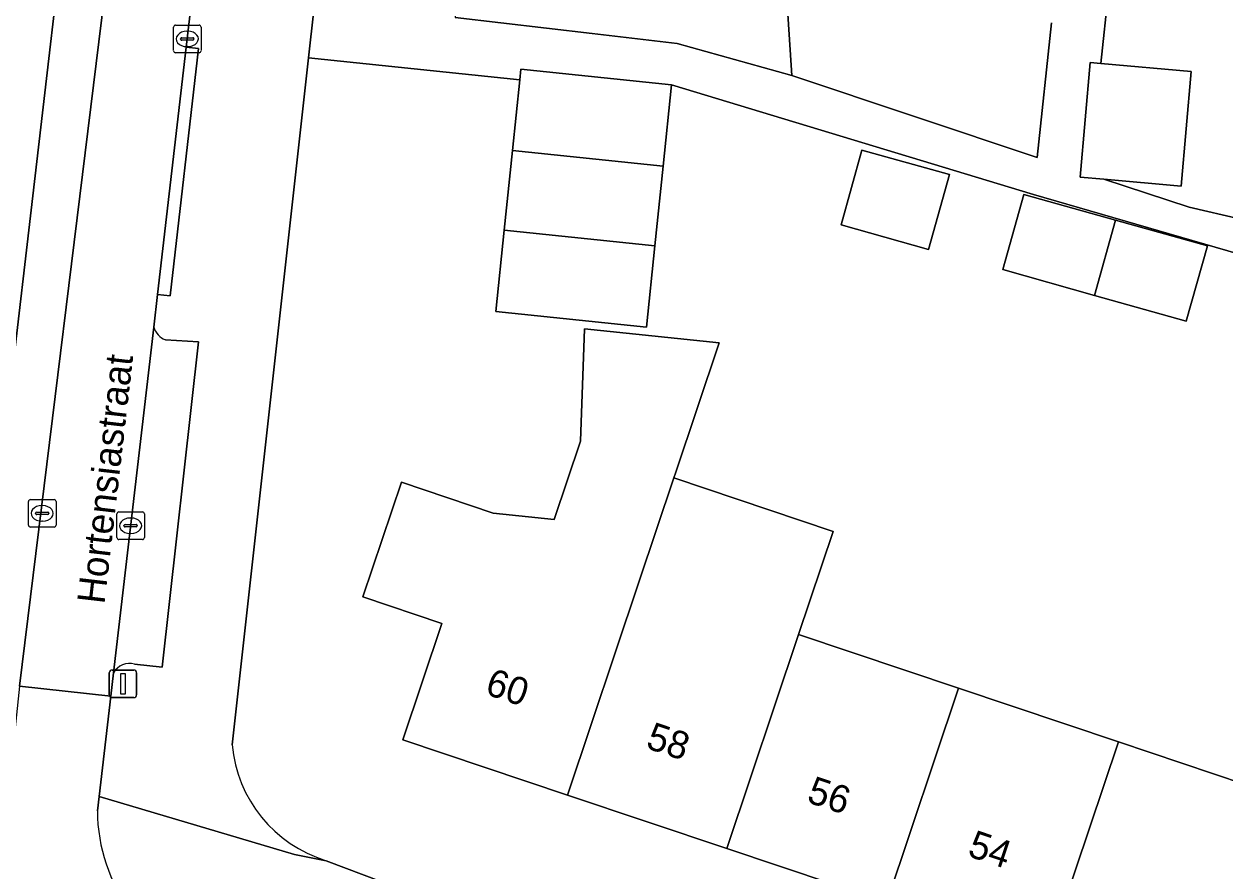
# Model space of a CAD drawing. Extents: x 161692 to 162379, y 380760 to 381678.
# Drawn here: x 162005.46 to 162049.01, y 380962.24 to 380992.94 of the extents above; entities that cross this region are included whole.
import ezdxf

# ---------------------------------------------------------------- set-up
doc = ezdxf.new("R2010")
doc.units = 0
for name, color, linetype in [('IMGEO_Erf', 7, 'Continuous'), ('IMGEO_Kolk', 7, 'Continuous'), ('IMGEO_Lichtmast', 7, 'Continuous'), ('IMGEO_Openbare_ruimte_label', 7, 'Continuous'), ('IMGEO_Pand', 7, 'Continuous'), ('IMGEO_Pand_nummerreeks', 7, 'Continuous'), ('IMGEO_Parkeervlak_open', 7, 'Continuous'), ('IMGEO_Rijbaan_lokaal_open', 7, 'Continuous'), ('IMGEO_Voetpad_open', 7, 'Continuous')]:
    doc.layers.add(name, color=color, linetype=linetype)

msp = doc.modelspace()

# ---------------------------------------------------------------- linework, layer by layer
at = {"layer": 'IMGEO_Erf'}
for points in [[(162049.147, 381005.801), (162046.062, 381006.135), (162045.505, 381000.982), (162048.591, 381000.649), (162048.242, 380997.421), (162047.85, 380993.799), (162044.785, 380994.13), (162044.509, 380991.51), (162047.791, 380991.221), (162047.425, 380987.065), (162044.621, 380987.312), (162047.712, 380986.308), (162057.079, 380984.131)], [(162032.862, 380997.951), (162033.305, 380991.072), (162042.204, 380988.097), (162042.717, 380992.979)], [(162058.561, 380975.708), (162055.003, 380977.223), (162049.4, 380978.891), (162051.158, 380984.129), (162042.064, 380986.765), (162028.946, 380990.739), (162028.64, 380987.79), (162028.341, 380984.905), (162028.036, 380981.959), (162022.566, 380982.526), (162022.872, 380985.472), (162023.171, 380988.357), (162023.436, 380990.915), (162015.772, 380991.71), (162013.002, 380966.811)], [(162053.992, 380955.32), (162048.296, 380957.232), (162042.545, 380959.162), (162036.746, 380961.108), (162030.947, 380963.054), (162025.17, 380964.992), (162019.198, 380966.996), (162020.614, 380971.218), (162017.75, 380972.18), (162019.144, 380976.334), (162022.475, 380975.216), (162024.69, 380974.984), (162025.641, 380977.82), (162025.786, 380981.89), (162030.665, 380981.384), (162029.084, 380976.665), (162029.026, 380976.493), (162034.805, 380974.553), (162033.55, 380970.812), (162039.349, 380968.866), (162045.148, 380966.92), (162050.899, 380964.99)], [(162016.411, 380962.617), (162029.526, 380957.667), (162046.576, 380951.828), (162059.92, 380947.792)]]:
    msp.add_lwpolyline(points, dxfattribs=at)
for points in [[(162035.089, 380985.66), (162035.847, 380988.372), (162039.017, 380987.485), (162038.259, 380984.773)], [(162040.952, 380984.038), (162041.715, 380986.766), (162045.042, 380985.835), (162048.374, 380984.903), (162047.611, 380982.175), (162044.279, 380983.107)]]:
    msp.add_lwpolyline(points, close=True, dxfattribs=at)
msp.add_arc((162017.857, 380967.275), 4.877, 185.4543, 252.7561, dxfattribs=at)
at = {"layer": 'IMGEO_Kolk'}
for p, q in [((162010.955, 380992.901), (162011.807, 380992.901)), ((162010.88, 380991.975), (162010.88, 380992.827)), ((162011.182, 380992.444), (162011.58, 380992.444)), ((162011.368, 380992.681), (162011.393, 380992.681)), ((162011.881, 380992.827), (162011.881, 380991.975)), ((162011.139, 380992.395), (162011.139, 380992.407)), ((162011.577, 380992.358), (162011.179, 380992.358)), ((162011.391, 380992.121), (162011.366, 380992.121)), ((162011.623, 380992.407), (162011.623, 380992.395)), ((162011.807, 380991.901), (162010.955, 380991.901)), ((162005.62, 380974.779), (162005.62, 380975.631)), ((162005.695, 380975.705), (162006.547, 380975.705)), ((162006.108, 380975.485), (162006.133, 380975.485)), ((162006.621, 380975.631), (162006.621, 380974.779)), ((162005.879, 380975.199), (162005.879, 380975.211)), ((162006.317, 380975.162), (162005.919, 380975.162)), ((162005.922, 380975.248), (162006.32, 380975.248)), ((162006.363, 380975.211), (162006.363, 380975.199)), ((162008.825, 380974.331), (162008.825, 380975.183)), ((162008.9, 380975.257), (162009.752, 380975.257)), ((162009.313, 380975.037), (162009.338, 380975.037)), ((162009.826, 380975.183), (162009.826, 380974.331)), ((162006.547, 380974.705), (162005.695, 380974.705)), ((162006.131, 380974.925), (162006.106, 380974.925)), ((162009.084, 380974.751), (162009.084, 380974.763)), ((162009.522, 380974.714), (162009.124, 380974.714)), ((162009.127, 380974.8), (162009.525, 380974.8)), ((162009.568, 380974.763), (162009.568, 380974.751)), ((162009.752, 380974.257), (162008.9, 380974.257)), ((162009.336, 380974.477), (162009.311, 380974.477))]:
    msp.add_line(p, q, dxfattribs=at)
for points in [[(162010.955, 380992.901), (162011.807, 380992.901)], [(162010.88, 380991.975), (162010.88, 380992.827)], [(162011.881, 380992.827), (162011.881, 380991.975)], [(162011.807, 380991.901), (162010.955, 380991.901)], [(162005.62, 380974.779), (162005.62, 380975.631)], [(162005.695, 380975.705), (162006.547, 380975.705)], [(162006.621, 380975.631), (162006.621, 380974.779)], [(162008.825, 380974.331), (162008.825, 380975.183)], [(162008.9, 380975.257), (162009.752, 380975.257)], [(162009.826, 380975.183), (162009.826, 380974.331)], [(162006.547, 380974.705), (162005.695, 380974.705)], [(162009.752, 380974.257), (162008.9, 380974.257)]]:
    msp.add_lwpolyline(points, dxfattribs=at)
for centre, radius, start, end in [((162010.957, 380992.825), 0.0765, 91.552, 178.448), ((162010.957, 380992.825), 0.0765, 91.552, 178.448), ((162011.805, 380992.825), 0.0765, 1.552, 88.448), ((162011.805, 380992.825), 0.0765, 1.552, 88.448), ((162011.179, 380992.404), 0.0403, 85.8775, 175.7526), ((162011.584, 380992.406), 0.0386, 1.7309, 96.639), ((162011.176, 380992.394), 0.0366, 178.938, 274.7102), ((162011.58, 380992.401), 0.043, 264.8664, 352.4533), ((162010.957, 380991.977), 0.0765, 181.552, 268.448), ((162010.957, 380991.977), 0.0765, 181.552, 268.448), ((162011.805, 380991.977), 0.0765, 271.552, 358.448), ((162011.805, 380991.977), 0.0765, 271.552, 358.448), ((162005.697, 380975.629), 0.0765, 91.552, 178.448), ((162005.697, 380975.629), 0.0765, 91.552, 178.448), ((162006.545, 380975.629), 0.0765, 1.552, 88.448), ((162006.545, 380975.629), 0.0765, 1.552, 88.448), ((162005.919, 380975.208), 0.0403, 85.8775, 175.7526), ((162005.916, 380975.198), 0.0366, 178.938, 274.7102), ((162006.32, 380975.205), 0.043, 264.8664, 352.4533), ((162006.324, 380975.21), 0.0386, 1.7309, 96.639), ((162008.902, 380975.181), 0.0765, 91.552, 178.448), ((162008.902, 380975.181), 0.0765, 91.552, 178.448), ((162009.75, 380975.181), 0.0765, 1.552, 88.448), ((162009.75, 380975.181), 0.0765, 1.552, 88.448), ((162005.697, 380974.781), 0.0765, 181.552, 268.448), ((162005.697, 380974.781), 0.0765, 181.552, 268.448), ((162006.545, 380974.781), 0.0765, 271.552, 358.448), ((162006.545, 380974.781), 0.0765, 271.552, 358.448), ((162009.124, 380974.76), 0.0403, 85.8775, 175.7526), ((162009.121, 380974.75), 0.0366, 178.938, 274.7102), ((162009.525, 380974.757), 0.043, 264.8664, 352.4533), ((162009.529, 380974.762), 0.0386, 1.7309, 96.639), ((162008.902, 380974.333), 0.0765, 181.552, 268.448), ((162008.902, 380974.333), 0.0765, 181.552, 268.448), ((162009.75, 380974.333), 0.0765, 271.552, 358.448), ((162009.75, 380974.333), 0.0765, 271.552, 358.448)]:
    msp.add_arc(centre, radius, start, end, dxfattribs=at)
for centre, major_axis, ratio, start_param, end_param in [((162011.367, 380992.401), (-0.387, 0.002), 0.722429, 4.712389, 7.853982), ((162011.392, 380992.401), (-0.39, 0.002), 0.717154, 1.570796, 4.712389), ((162006.107, 380975.205), (-0.387, 0.002), 0.722429, 4.712389, 7.853982), ((162006.132, 380975.205), (-0.39, 0.002), 0.717154, 1.570796, 4.712389), ((162009.312, 380974.757), (-0.387, 0.002), 0.722429, 4.712389, 7.853982), ((162009.337, 380974.757), (-0.39, 0.002), 0.717154, 1.570796, 4.712389)]:
    msp.add_ellipse(centre, major_axis=major_axis, ratio=ratio, start_param=start_param, end_param=end_param, dxfattribs=at)
at = {"layer": 'IMGEO_Lichtmast'}
for p, q in [((162008.553, 380968.627), (162008.553, 380969.427)), ((162008.553, 380969.427), (162008.553, 380968.627)), ((162008.653, 380969.527), (162009.443, 380969.527)), ((162009.443, 380969.527), (162008.653, 380969.527)), ((162009.543, 380969.427), (162009.543, 380968.627)), ((162009.543, 380968.627), (162009.543, 380969.427)), ((162009.443, 380968.527), (162008.653, 380968.527)), ((162008.653, 380968.527), (162009.443, 380968.527))]:
    msp.add_line(p, q, dxfattribs=at)
msp.add_lwpolyline([(162008.973, 380969.402), (162009.123, 380969.402), (162009.123, 380968.652), (162008.973, 380968.652), (162008.973, 380969.402)], dxfattribs=at)
for centre, start, end in [((162008.653, 380969.427), 90, 180), ((162008.653, 380969.427), 90, 180), ((162009.443, 380969.427), 0, 90), ((162009.443, 380969.427), 360, 90), ((162008.653, 380968.627), 180, 270), ((162008.653, 380968.627), 180, 270), ((162009.443, 380968.627), 270, 0), ((162009.443, 380968.627), 270, 0)]:
    msp.add_arc(centre, 0.1, start, end, dxfattribs=at)
at = {"layer": 'IMGEO_Pand'}
for points in [[(162032.401, 380998.003), (162029.799, 380998.3), (162027.322, 380998.583), (162021.786, 380999.214), (162021.098, 380993.178), (162026.065, 380992.596), (162029.143, 380992.236), (162033.305, 380991.072), (162032.862, 380997.951)], [(162028.946, 380990.739), (162023.477, 380991.306), (162023.436, 380990.915), (162023.171, 380988.357), (162028.64, 380987.79)], [(162047.791, 380991.221), (162044.509, 380991.51), (162044.13, 380991.543), (162043.764, 380987.387), (162044.621, 380987.312), (162047.425, 380987.065)], [(162023.171, 380988.357), (162022.872, 380985.472), (162028.341, 380984.905), (162028.64, 380987.79)], [(162035.089, 380985.66), (162038.259, 380984.773), (162039.017, 380987.485), (162035.847, 380988.372)], [(162045.042, 380985.835), (162041.715, 380986.766), (162040.952, 380984.038), (162044.279, 380983.107)], [(162022.872, 380985.472), (162022.566, 380982.526), (162028.036, 380981.959), (162028.341, 380984.905)], [(162045.042, 380985.835), (162044.279, 380983.107), (162047.611, 380982.175), (162048.374, 380984.903)], [(162029.026, 380976.493), (162029.084, 380976.665), (162030.665, 380981.384), (162025.786, 380981.89), (162025.641, 380977.82), (162024.69, 380974.984), (162022.475, 380975.216), (162019.144, 380976.334), (162017.75, 380972.18), (162020.614, 380971.218), (162019.198, 380966.996), (162025.17, 380964.992), (162027.772, 380972.751)], [(162033.55, 380970.812), (162034.805, 380974.553), (162029.026, 380976.493), (162027.772, 380972.751), (162025.17, 380964.992), (162030.947, 380963.054)], [(162039.349, 380968.866), (162033.55, 380970.812), (162030.947, 380963.054), (162036.746, 380961.108)], [(162042.545, 380959.162), (162045.148, 380966.92), (162039.349, 380968.866), (162036.746, 380961.108)], [(162042.545, 380959.162), (162048.296, 380957.232), (162050.899, 380964.99), (162045.148, 380966.92)]]:
    msp.add_lwpolyline(points, close=True, dxfattribs=at)
at = {"layer": 'IMGEO_Parkeervlak_open'}
for points in [[(162005.298, 380968.939), (162008.477, 380994.755), (162008.814, 380997.445)], [(162008.247, 380997.073), (162007.002, 380997.196), (162003.756, 380969.496), (162004.709, 380969.385)], [(162010.162, 380981.956), (162008.704, 380969.423)], [(162009.469, 380969.744), (162010.473, 380969.633), (162011.791, 380981.419), (162010.585, 380981.491)]]:
    msp.add_lwpolyline(points, dxfattribs=at)
for centre, radius, start, end in [((162010.869, 380982.174), 0.74, 197.1604, 247.4238), ((162009.299, 380969.078), 0.688, 75.6643, 149.8623)]:
    msp.add_arc(centre, radius, start, end, dxfattribs=at)
at = {"layer": 'IMGEO_Rijbaan_lokaal_open'}
msp.add_lwpolyline([(162011.344, 380992.103), (162011.644, 380994.671), (162012.264, 381000), (162013.811, 381012.386), (162015.661, 381028.223), (162016.939, 381039.955), (162013.852, 381040.249), (162012.542, 381029.228), (162010.698, 381013.15), (162009.735, 381005.057), (162009.423, 381002.428), (162009.134, 381000), (162008.854, 380997.766), (162008.814, 380997.445), (162008.477, 380994.755), (162005.298, 380968.939), (162008.606, 380968.584), (162008.704, 380969.423), (162010.162, 380981.956), (162010.301, 380983.14)], close=True, dxfattribs=at)
msp.add_lwpolyline([(162008.121, 380964.42), (162008.182, 380964.946), (162008.606, 380968.584), (162005.298, 380968.939), (162005.053, 380966.634)], dxfattribs=at)
msp.add_arc((162014.175, 380964.431), 6.054, 180.1059, 253.3292, dxfattribs=at)
at = {"layer": 'IMGEO_Voetpad_open'}
for points in [[(162026.345, 381148.219), (162026.366, 381148.384), (162026.485, 381149.36), (162021.813, 381150.411), (162020.89, 381142.109), (162015.25, 381092.109), (162015.033, 381090.181), (162009.512, 381041.24), (162009.346, 381039.768), (162009.322, 381039.552), (162005.116, 381004.283), (162004.93, 381002.725), (162004.605, 381000), (162001.24, 380971.782), (162003.756, 380969.496), (162007.002, 380997.196), (162008.247, 380997.073)], [(162013.002, 380966.811), (162015.772, 380991.71), (162015.965, 380993.447), (162015.99, 380993.672), (162016.694, 381000), (162018.038, 381009.86), (162021.693, 381042.175), (162021.85, 381043.562), (162025.499, 381075.815)], [(162057.079, 380984.131), (162047.712, 380986.308), (162044.621, 380987.312), (162043.764, 380987.387), (162044.13, 380991.543), (162044.509, 380991.51), (162044.785, 380994.13), (162044.593, 380994.151), (162044.987, 380997.799), (162045.333, 381001.001), (162045.505, 381000.982), (162046.062, 381006.135), (162045.977, 381006.144), (162046.402, 381010.075), (162046.748, 381013.277), (162046.833, 381013.268), (162047.364, 381018.172), (162047.8, 381022.2), (162048.146, 381025.402), (162048.765, 381030.327), (162049.203, 381034.376)], [(162011.644, 380994.671), (162011.344, 380992.103), (162011.787, 380992.051), (162010.764, 380983.086), (162010.301, 380983.14), (162010.162, 380981.956)], [(162015.965, 380993.447), (162015.772, 380991.71), (162023.436, 380990.915), (162023.477, 380991.306), (162028.946, 380990.739), (162042.064, 380986.765), (162051.158, 380984.129)], [(162042.717, 380992.979), (162042.204, 380988.097), (162033.305, 380991.072), (162029.143, 380992.236), (162026.065, 380992.596), (162021.098, 380993.178)], [(162010.585, 380981.491), (162011.791, 380981.419), (162010.473, 380969.633), (162009.469, 380969.744)], [(162008.704, 380969.423), (162008.606, 380968.584), (162008.182, 380964.946), (162015.272, 380962.845), (162016.411, 380962.617)], [(162059.92, 380947.792), (162046.576, 380951.828), (162029.526, 380957.667), (162016.411, 380962.617), (162015.272, 380962.845), (162008.182, 380964.946), (162008.121, 380964.42)]]:
    msp.add_lwpolyline(points, dxfattribs=at)
msp.add_lwpolyline([(162011.344, 380992.103), (162010.301, 380983.14), (162010.764, 380983.086), (162011.787, 380992.051)], close=True, dxfattribs=at)
for centre, radius, start, end in [((162010.869, 380982.174), 0.74, 197.1604, 247.4238), ((162009.299, 380969.078), 0.688, 75.6643, 149.8623), ((162017.857, 380967.275), 4.877, 185.4543, 252.7561), ((162014.175, 380964.431), 6.054, 180.1059, 253.3292)]:
    msp.add_arc(centre, radius, start, end, dxfattribs=at)

# ---------------------------------------------------------------- texts
at = {"layer": 'IMGEO_Openbare_ruimte_label'}
msp.add_text('Hortensiastraat', height=1, rotation=83.394, dxfattribs=at).set_placement((162008.375, 380971.892))
at = {"layer": 'IMGEO_Pand_nummerreeks'}
for s, rotation, p in [('60', 341.4476, (162022.136, 380968.668)), ('58', 341.4476, (162027.971, 380966.71)), ('56', 341.4502, (162033.803, 380964.753)), ('54', 341.4502, (162039.638, 380962.795))]:
    msp.add_text(s, height=1, rotation=rotation, dxfattribs=at).set_placement(p)

doc.saveas('drawing.dxf')
